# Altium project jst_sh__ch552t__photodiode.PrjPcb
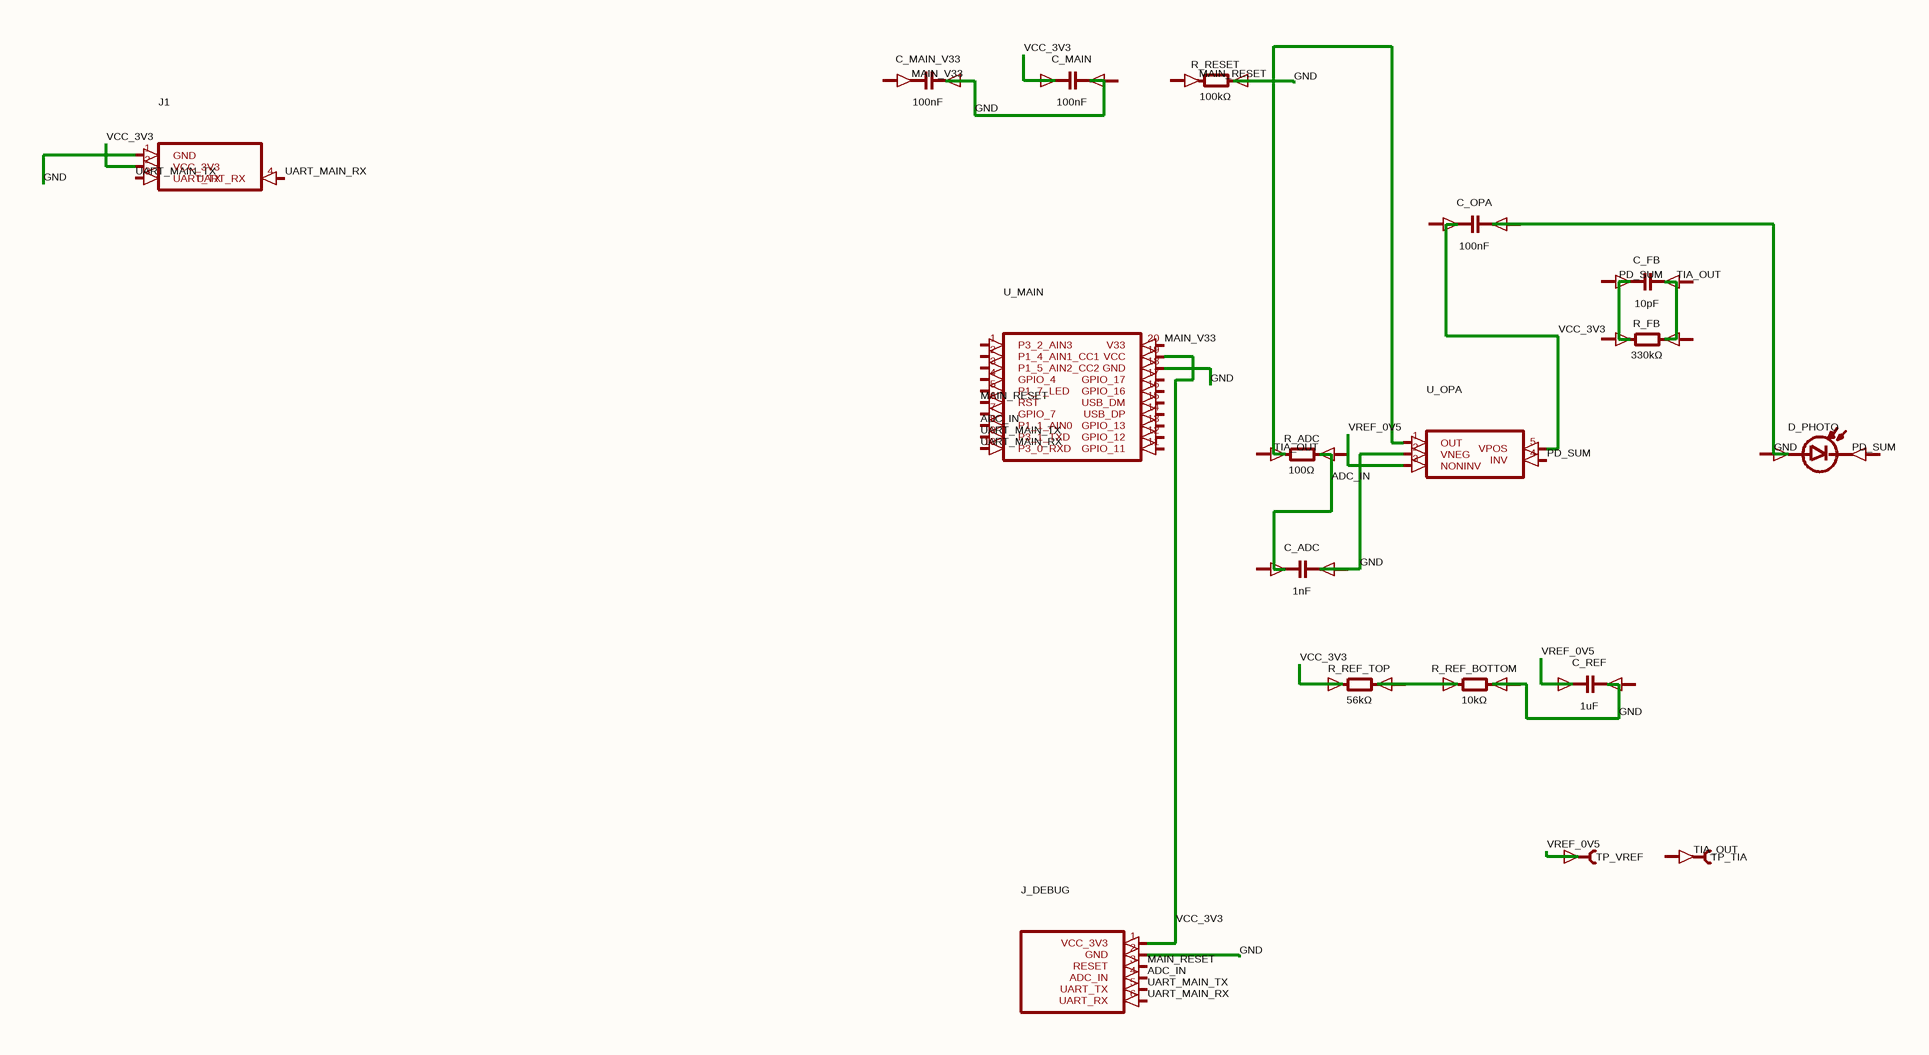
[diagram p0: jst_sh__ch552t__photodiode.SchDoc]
1 sheet, 18 parts. Net scope: global (net labels, ports and power ports of the same name join across sheets).
Board file: jst_sh__ch552t__photodiode.PcbDoc

## Sheet jst_sh__ch552t__photodiode.SchDoc
size 212 x 135 mm

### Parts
C_ADC  1nF
C_FB  10pF
C_MAIN  100nF
C_MAIN_V33  100nF
C_OPA  100nF
C_REF  1uF
D_PHOTO  (no value)
J1  (no value)
J_DEBUG  (no value)
R_ADC  100Ω
R_FB  330kΩ
R_REF_BOTTOM  10kΩ
R_REF_TOP  56kΩ
R_RESET  100kΩ
TP_TIA  (no value)
TP_VREF  (no value)
U_MAIN  (no value)
U_OPA  (no value)

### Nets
ADC_IN: J_DEBUG.4(ADC_IN) U_MAIN.8(P1_1_AIN0)
GND: C_ADC.2(neg) C_MAIN_V33.2(neg) C_OPA.2(neg) C_REF.1(pos) J1.1(GND) J_DEBUG.2(GND) R_ADC.2(cathode) R_REF_BOTTOM.2(cathode) R_RESET.2(cathode) TP_VREF.1(pin1) U_MAIN.18(GND) U_OPA.2(VNEG) U_OPA.3(NONINV)  [also labelled VREF_0V5]
MAIN_RESET: J_DEBUG.3(RESET) U_MAIN.6(RST)
MAIN_V33: U_MAIN.20(V33)
PD_SUM: U_OPA.4(INV)
TIA_OUT: U_OPA.1(OUT)
UART_MAIN_RX: J1.4(UART_RX) J_DEBUG.6(UART_RX) U_MAIN.10(P3_0_RXD)
UART_MAIN_TX: J1.3(UART_TX) J_DEBUG.5(UART_TX) U_MAIN.9(P3_1_TXD)
VCC_3V3: C_MAIN.1(pos) J1.2(VCC_3V3) J_DEBUG.1(VCC_3V3) R_REF_TOP.1(anode) U_MAIN.19(VCC) U_OPA.5(VPOS)
NetR_REF_BOTTOM_1: R_REF_BOTTOM.1(anode) R_REF_TOP.2(cathode)

Not connected (* = marked no-connect by the designer): C_ADC 1(pos); C_FB 1(pos) 2(neg); C_MAIN 2(neg); C_MAIN_V33 1(pos); C_OPA 1(pos); C_REF 2(neg); D_PHOTO 1(anode) 2(cathode); R_ADC 1(anode); R_FB 1(anode) 2(cathode); R_RESET 1(anode); TP_TIA 1(pin1); U_MAIN 1(P3_2_AIN3) 2(P1_4_AIN1_CC1) 3(P1_5_AIN2_CC2) 4(GPIO_4) 5(P1_7_LED) 7(GPIO_7) 11(GPIO_11) 12(GPIO_12) 13(GPIO_13) 14(USB_DP) 15(USB_DM) 16(GPIO_16) 17(GPIO_17)

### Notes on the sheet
- Labels drawn without touching a wire or pin: MAIN_RESET, MAIN_V33, PD_SUM, TIA_OUT

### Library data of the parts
C_ADC C_FB C_MAIN C_MAIN_V33 C_OPA C_REF = capacitor_right
D_PHOTO = photodiode_horz
J1 = J1
J_DEBUG = J_DEBUG
R_ADC R_FB R_REF_BOTTOM R_REF_TOP R_RESET = boxresistor_right
TP_TIA TP_VREF = testpoint_right
U_MAIN = U_MAIN
U_OPA = U_OPA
